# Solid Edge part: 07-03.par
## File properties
Author: edge
Template: jis part.par
Last saved by: edge
Revision: 25
Application: Solid Edge
Density: 7833.000 kg/m^3
Accuracy: 0.990
文書内容のタイプ: 0
Material: 鋼鉄
面のスタイル: Steel
塗りつぶしのスタイル: ANSI32(Steel)
バーチャルスタイル: 鋼鉄 機械仕上げ
Coef. of Thermal Exp: 0.0
Thermal Conductivity: 32.0
Specific Heat: 481.0
Modulus of Elasticity: 199947953000.0
Poisson's Ratio: 0.29
Yield Stress: 262000766.0
Ultimate Stress: 358527364.0
Elongation: 0.0
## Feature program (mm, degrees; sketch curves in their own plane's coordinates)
sketch for "unnamed Protrusion 1" plane through (0, 0, 0) normal (1, 0, 0) x-axis (0, 1, 0)
  line (0, 0) -> (-80, 0)
  line (-80, 0) -> (-80, 180)
  line (-80, 180) -> (0, 180)
  line (0, 180) -> (0, 0)
extrude "unnamed Protrusion 1" add finite 160 symmetric
thinwall "Thinwall_1"  Thickness = 20 mm
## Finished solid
Body 1: solid body, 8 faces, 18 edges, 12 vertices.
  Faces by surface: plane 8
  Edges by curve: line 18
Bounding box of the edges (mm): 160.000 x 80.000 x 180.000, from (-80, -80, 0) to (80, 0, 180).
Planar faces by outward normal: +x 1, +y 1, +z 2, -x 1, -y 2, -z 1
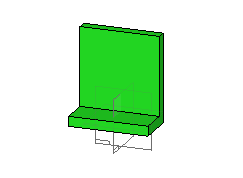
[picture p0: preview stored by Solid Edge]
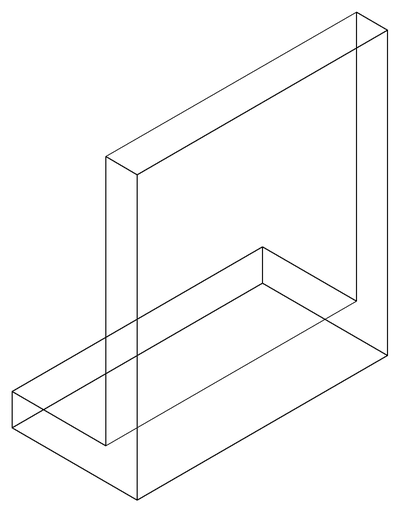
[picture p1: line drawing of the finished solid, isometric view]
